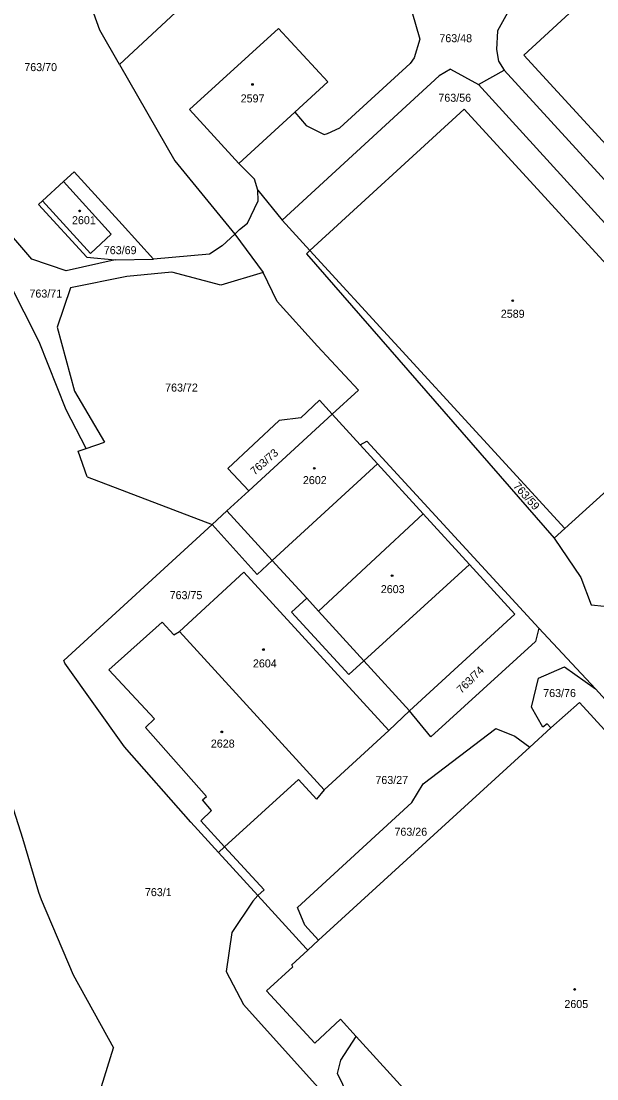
# Model space of a CAD drawing. Extents: x -735249 to -729401, y -1124843 to -1121828.
# Drawn here: x -733806.2 to -733683.8, y -1124377.1 to -1124152.4 of the extents above; entities that cross this region are included whole.
import ezdxf

# ---------------------------------------------------------------- set-up
doc = ezdxf.new("R2010")
doc.units = 0
for name, color, linetype in [('Vrstva 1', 7, 'Continuous'), ('Vrstva 18', 7, 'Continuous'), ('Vrstva 19', 7, 'Continuous'), ('Vrstva 25', 7, 'Continuous'), ('Vrstva 4', 7, 'Continuous')]:
    doc.layers.add(name, color=color, linetype=linetype)

msp = doc.modelspace()

# ---------------------------------------------------------------- linework, layer by layer
at = {"layer": 'Vrstva 1'}
for points in [[(-733789.42, -1124154.27), (-733797.89, -1124130.77)], [(-733699.33, -1124159.59), (-733670.27, -1124132.8)], [(-733767.36, -1124144.94), (-733785.22, -1124161.62)], [(-733723.14, -1124150.36), (-733721.44, -1124156.2)], [(-733702.79, -1124150.63), (-733704.9, -1124154.4)], [(-733785.22, -1124161.62), (-733789.42, -1124154.27)], [(-733770.39, -1124171.16), (-733751.43, -1124153.94)], [(-733751.43, -1124153.94), (-733740.95, -1124165.27)], [(-733704.9, -1124154.4), (-733705.09, -1124158.37)], [(-733721.44, -1124156.2), (-733722.61, -1124160.2)], [(-733722.61, -1124160.2), (-733723.44, -1124161.37)], [(-733705.09, -1124158.37), (-733704.7, -1124160.89)], [(-733647.62, -1124215.93), (-733699.33, -1124159.59)], [(-733785.22, -1124161.62), (-733773.51, -1124182.08)], [(-733738.44, -1124175.02), (-733723.44, -1124161.37)], [(-733714.93, -1124162.61), (-733717.32, -1124163.99)], [(-733714.93, -1124162.61), (-733708.97, -1124165.86)], [(-733704.7, -1124160.89), (-733703.47, -1124162.81)], [(-733717.32, -1124163.99), (-733750.7, -1124194.68)], [(-733708.97, -1124165.86), (-733703.47, -1124162.81)], [(-733703.47, -1124162.81), (-733679.8, -1124188.61)], [(-733740.95, -1124165.27), (-733747.99, -1124171.7)], [(-733681.37, -1124196.06), (-733708.97, -1124165.86)], [(-733759.92, -1124182.6), (-733770.39, -1124171.16)], [(-733747.99, -1124171.7), (-733759.92, -1124182.6)], [(-733747.99, -1124171.7), (-733745.57, -1124174.57)], [(-733744.77, -1124201.13), (-733712.01, -1124171.1)], [(-733712.01, -1124171.1), (-733657.65, -1124230.34)], [(-733745.57, -1124174.57), (-733741.73, -1124176.45)], [(-733741.07, -1124176.21), (-733738.44, -1124175.02)], [(-733741.73, -1124176.45), (-733741.07, -1124176.21)], [(-733773.51, -1124182.08), (-733760.75, -1124197.63)], [(-733756.59, -1124185.97), (-733759.92, -1124182.6)], [(-733794.85, -1124184.38), (-733797.14, -1124186.46)], [(-733784.71, -1124195.56), (-733794.85, -1124184.38)], [(-733797.14, -1124186.46), (-733801.63, -1124190.56)], [(-733797.14, -1124186.46), (-733787, -1124197.65)], [(-733755.85, -1124188.29), (-733756.59, -1124185.97)], [(-733755.8, -1124190.56), (-733755.85, -1124188.29)], [(-733755.85, -1124188.29), (-733750.7, -1124194.68)], [(-733801.63, -1124190.56), (-733802.44, -1124191.3)], [(-733802.44, -1124191.3), (-733792.19, -1124202.55)], [(-733791.42, -1124201.73), (-733801.63, -1124190.56)], [(-733758.01, -1124195.26), (-733755.8, -1124190.56)], [(-733803.91, -1124202.94), (-733811.26, -1124194.42)], [(-733777.99, -1124202.97), (-733784.71, -1124195.56)], [(-733759.74, -1124196.63), (-733758.01, -1124195.26)], [(-733750.7, -1124194.68), (-733744.77, -1124201.13)], [(-733787, -1124197.65), (-733791.42, -1124201.73)], [(-733760.75, -1124197.63), (-733763.43, -1124200.11)], [(-733760.75, -1124197.63), (-733759.74, -1124196.63)], [(-733760.75, -1124197.63), (-733754.74, -1124205.8)], [(-733763.43, -1124200.11), (-733766.11, -1124201.87)], [(-733802.32, -1124220.47), (-733811.97, -1124201.57)], [(-733796.57, -1124205.4), (-733803.91, -1124202.94)], [(-733786.17, -1124203.07), (-733796.57, -1124205.4)], [(-733792.19, -1124202.55), (-733786.17, -1124203.07)], [(-733786.17, -1124203.07), (-733777.99, -1124202.97)], [(-733766.11, -1124201.87), (-733777.99, -1124202.97)], [(-733744.77, -1124201.13), (-733745.51, -1124201.8)], [(-733745.51, -1124201.8), (-733692.84, -1124262.2)], [(-733744.77, -1124201.13), (-733690.59, -1124260.14)], [(-733783.68, -1124206.59), (-733795.66, -1124209.06)], [(-733774.13, -1124205.73), (-733783.68, -1124206.59)], [(-733763.68, -1124208.46), (-733774.13, -1124205.73)], [(-733754.74, -1124205.8), (-733763.68, -1124208.46)], [(-733751.76, -1124211.9), (-733754.74, -1124205.8)], [(-733795.66, -1124209.06), (-733798.5, -1124217.36)], [(-733751.76, -1124211.9), (-733743.13, -1124221.41)], [(-733798.5, -1124217.36), (-733794.79, -1124230.97)], [(-733796.57, -1124234.93), (-733802.32, -1124220.47)], [(-733743.13, -1124221.41), (-733734.43, -1124230.78)], [(-733794.79, -1124230.97), (-733788.46, -1124241.81)], [(-733734.43, -1124230.78), (-733740.02, -1124235.9)], [(-733690.59, -1124260.14), (-733657.65, -1124230.34)], [(-733742.73, -1124232.93), (-733746.74, -1124236.63)], [(-733740.02, -1124235.9), (-733742.73, -1124232.93)], [(-733792.31, -1124243.16), (-733796.57, -1124234.93)], [(-733740.02, -1124235.9), (-733757.74, -1124252.14)], [(-733746.74, -1124236.63), (-733751.33, -1124237.18)], [(-733740.02, -1124235.9), (-733734.09, -1124242.38)], [(-733751.33, -1124237.18), (-733762.2, -1124247.42)], [(-733794.03, -1124243.76), (-733792.31, -1124243.16)], [(-733792.31, -1124243.16), (-733788.46, -1124241.81)], [(-733734.09, -1124242.38), (-733732.69, -1124241.57)], [(-733730.39, -1124246.44), (-733734.09, -1124242.38)], [(-733732.69, -1124241.57), (-733696.13, -1124281.31)], [(-733792.14, -1124249.16), (-733794.03, -1124243.76)], [(-733757.74, -1124252.14), (-733762.2, -1124247.42)], [(-733730.39, -1124246.44), (-733752.79, -1124266.96)], [(-733720.69, -1124257.05), (-733730.39, -1124246.44)], [(-733792.14, -1124249.16), (-733765.57, -1124259.32)], [(-733762.42, -1124256.43), (-733757.74, -1124252.14)], [(-733765.57, -1124259.32), (-733762.42, -1124256.43)], [(-733710.86, -1124267.8), (-733720.69, -1124257.05)], [(-733797.11, -1124288.22), (-733765.57, -1124259.32)], [(-733765.57, -1124259.32), (-733756, -1124269.9)], [(-733692.84, -1124262.2), (-733690.59, -1124260.14)], [(-733692.84, -1124262.2), (-733687.2, -1124270.57)], [(-733756, -1124269.9), (-733752.79, -1124266.96)], [(-733752.79, -1124266.96), (-733745.46, -1124274.98)], [(-733701.21, -1124278.37), (-733710.86, -1124267.8)], [(-733772.52, -1124282.04), (-733758.79, -1124269.46)], [(-733758.79, -1124269.46), (-733727.99, -1124303.09)], [(-733687.2, -1124270.57), (-733685, -1124276.39)], [(-733745.46, -1124274.98), (-733748.67, -1124277.91)], [(-733685, -1124276.39), (-733679.48, -1124276.94)], [(-733748.67, -1124277.91), (-733736.51, -1124291.21)], [(-733723.58, -1124298.91), (-733701.21, -1124278.37)], [(-733787.51, -1124290.18), (-733776.21, -1124280.04)], [(-733776.21, -1124280.04), (-733773.67, -1124282.78)], [(-733696.13, -1124281.31), (-733696.83, -1124284.15)], [(-733696.13, -1124281.31), (-733684.1, -1124294.21)], [(-733773.67, -1124282.78), (-733772.52, -1124282.04)], [(-733772.52, -1124282.04), (-733741.73, -1124315.7)], [(-733696.83, -1124284.15), (-733719.07, -1124304.42)], [(-733796.85, -1124288.74), (-733797.11, -1124288.22)], [(-733736.51, -1124291.21), (-733733.3, -1124288.28)], [(-733733.3, -1124288.28), (-733723.58, -1124298.91)], [(-733784.22, -1124306.55), (-733796.85, -1124288.74)], [(-733777.84, -1124300.6), (-733787.51, -1124290.18)], [(-733696.19, -1124291.98), (-733690.64, -1124289.52)], [(-733690.64, -1124289.52), (-733684.1, -1124294.21)], [(-733697.66, -1124298.11), (-733696.19, -1124291.98)], [(-733684.1, -1124294.21), (-733651.77, -1124329.79)], [(-733693.58, -1124302.52), (-733687.48, -1124297.1)], [(-733687.48, -1124297.1), (-733679.15, -1124306.24)], [(-733723.58, -1124298.91), (-733727.99, -1124303.09)], [(-733719.07, -1124304.42), (-733723.58, -1124298.91)], [(-733695.3, -1124302.35), (-733697.66, -1124298.11)], [(-733779.71, -1124302.43), (-733777.84, -1124300.6)], [(-733694.37, -1124301.67), (-733695.3, -1124302.35)], [(-733693.58, -1124302.52), (-733694.37, -1124301.67)], [(-733766.79, -1124317.07), (-733779.71, -1124302.43)], [(-733727.99, -1124303.09), (-733741.73, -1124315.7)], [(-733720.72, -1124314.39), (-733705.28, -1124302.63)], [(-733705.28, -1124302.63), (-733701.22, -1124304.31)], [(-733698.06, -1124306.62), (-733693.58, -1124302.52)], [(-733701.22, -1124304.31), (-733698.06, -1124306.62)], [(-733770.07, -1124322.56), (-733784.22, -1124306.55)], [(-733698.06, -1124306.62), (-733742.93, -1124347.58)], [(-733747.18, -1124313.48), (-733762.93, -1124327.82)], [(-733743.36, -1124317.63), (-733747.18, -1124313.48)], [(-733723.13, -1124318.38), (-733720.72, -1124314.39)], [(-733767.6, -1124317.83), (-733766.79, -1124317.07)], [(-733741.73, -1124315.7), (-733743.36, -1124317.63)], [(-733808.27, -1124318.26), (-733807.75, -1124319.94), (-733805.9, -1124325.94), (-733802.47, -1124337.44), (-733801.87, -1124338.97)], [(-733765.66, -1124320.08), (-733767.6, -1124317.83)], [(-733747.45, -1124340.64), (-733723.13, -1124318.38)], [(-733767.98, -1124322.25), (-733765.66, -1124320.08)], [(-733762.93, -1124327.82), (-733767.98, -1124322.25)], [(-733764.19, -1124328.97), (-733770.07, -1124322.56)], [(-733762.93, -1124327.82), (-733764.19, -1124328.97)], [(-733754.48, -1124336.94), (-733762.93, -1124327.82)], [(-733754.48, -1124336.94), (-733755.82, -1124338.1)], [(-733801.87, -1124338.97), (-733795.13, -1124355.01)], [(-733756.93, -1124339.32), (-733761.37, -1124345.96)], [(-733755.82, -1124338.1), (-733756.93, -1124339.32)], [(-733755.82, -1124338.1), (-733745.56, -1124349.39)], [(-733745.84, -1124344.4), (-733747.45, -1124340.64)], [(-733742.93, -1124347.58), (-733745.84, -1124344.4)], [(-733761.37, -1124345.96), (-733762.56, -1124354.24)], [(-733745.25, -1124349.73), (-733742.93, -1124347.58)], [(-733748.65, -1124352.87), (-733745.25, -1124349.73)], [(-733745.56, -1124349.39), (-733745.25, -1124349.73)], [(-733753.98, -1124358.39), (-733748.41, -1124353.3)], [(-733748.41, -1124353.3), (-733748.65, -1124352.87)], [(-733795.13, -1124355.01), (-733786.51, -1124370.48)], [(-733762.56, -1124354.24), (-733758.9, -1124361.25)], [(-733743.75, -1124369.48), (-733753.98, -1124358.39)], [(-733758.9, -1124361.25), (-733739.84, -1124382.45)], [(-733738.31, -1124364.38), (-733743.75, -1124369.48)], [(-733734.94, -1124368.08), (-733738.31, -1124364.38)], [(-733738.21, -1124373.1), (-733734.94, -1124368.08)], [(-733723.4, -1124380.76), (-733734.94, -1124368.08)], [(-733792.07, -1124388.37), (-733789.06, -1124378.71), (-733786.51, -1124370.48)], [(-733738.93, -1124375.97), (-733738.21, -1124373.1)], [(-733736.62, -1124380.59), (-733738.93, -1124375.97)]]:
    msp.add_lwpolyline(points, dxfattribs=at)
at = {"layer": 'Vrstva 25'}
for centre in [(-733756.98, -1124165.82), (-733793.73, -1124192.68), (-733701.68, -1124211.76), (-733743.85, -1124247.37), (-733727.31, -1124270.19), (-733754.65, -1124285.87), (-733763.5, -1124303.36), (-733688.52, -1124358.08)]:
    msp.add_circle(centre, 0.175, dxfattribs=at)
at = {"layer": 'Vrstva 4'}
for points in [[(-733752.79, -1124266.96), (-733762.42, -1124256.43)], [(-733720.69, -1124257.05), (-733742.93, -1124277.75)], [(-733733.3, -1124288.28), (-733710.86, -1124267.8)], [(-733745.46, -1124274.98), (-733742.93, -1124277.75)], [(-733742.93, -1124277.75), (-733733.3, -1124288.28)], [(-733755.82, -1124338.1), (-733764.19, -1124328.97)]]:
    msp.add_lwpolyline(points, dxfattribs=at)

# ---------------------------------------------------------------- texts
at = {"layer": 'Vrstva 18'}
for s, p in [('763/48', (-733717.26, -1124156.85)), ('763/70', (-733805.48, -1124162.99)), ('763/56', (-733717.47, -1124169.5)), ('763/69', (-733788.58, -1124201.88)), ('763/71', (-733804.39, -1124211.1)), ('763/72', (-733775.55, -1124231.07)), ('763/75', (-733774.59, -1124275.17)), ('763/76', (-733695.19, -1124295.97)), ('763/27', (-733730.86, -1124314.43)), ('763/26', (-733726.81, -1124325.43)), ('763/1', (-733779.85, -1124338.26))]:
    msp.add_text(s, height=1.7, dxfattribs=at).set_placement(p)
for s, rotation, p in [('763/73', 41.50033, (-733756.533, -1124248.928)), ('763/59', 311.80248, (-733701.688, -1124251.245)), ('763/74', 44.40035, (-733712.598, -1124295.318))]:
    msp.add_text(s, height=1.7, rotation=rotation, dxfattribs=at).set_placement(p)
at = {"layer": 'Vrstva 19'}
for s, p in [('2597', (-733759.49, -1124169.64)), ('2601', (-733795.35, -1124195.51)), ('2589', (-733704.2, -1124215.39)), ('2602', (-733746.27, -1124250.73)), ('2603', (-733729.71, -1124273.89)), ('2604', (-733756.89, -1124289.67)), ('2628', (-733765.83, -1124306.7)), ('2605', (-733690.69, -1124362.03))]:
    msp.add_text(s, height=1.7, dxfattribs=at).set_placement(p)

doc.saveas('drawing.dxf')
